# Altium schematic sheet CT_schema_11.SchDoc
size 281 x 153 mm
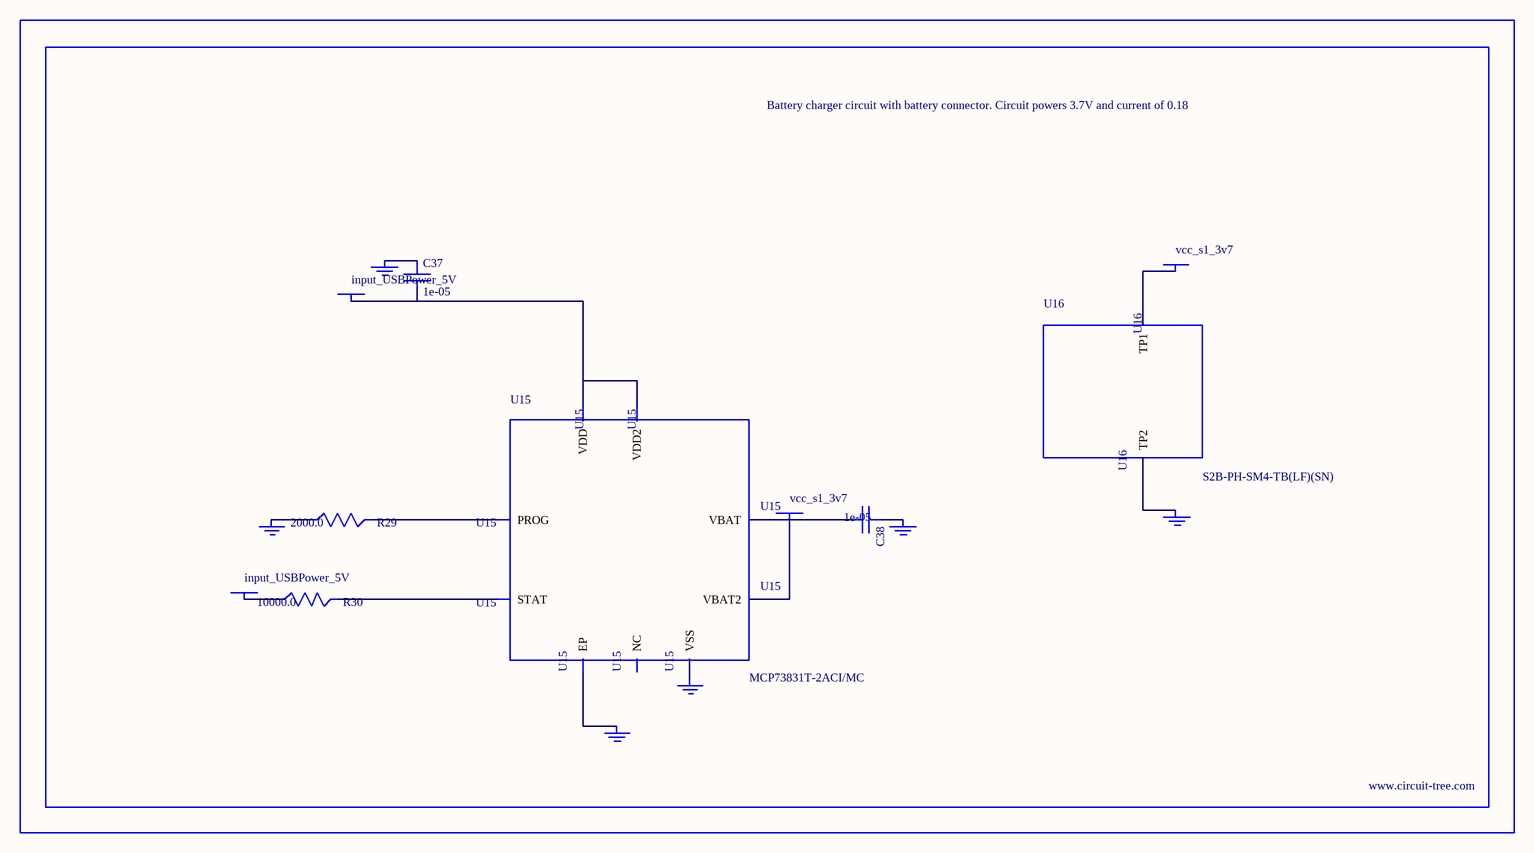
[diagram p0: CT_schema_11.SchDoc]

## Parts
BORDER10  (no value)
C37  1e-05  [C1206]
C38  1e-05  [C1206]
GND_INSTANCE_10_0  (no value)
GND_INSTANCE_10_1  (no value)
GND_INSTANCE_10_2  (no value)
GND_INSTANCE_10_3  (no value)
GND_INSTANCE_10_4  (no value)
GND_INSTANCE_10_5  (no value)
POWER_INSTANCE_10_0  input_USBPower_5V
POWER_INSTANCE_10_1  input_USBPower_5V
POWER_INSTANCE_10_2  vcc_s1_3v7
POWER_INSTANCE_10_3  vcc_s1_3v7
R29  2000.0  [R0603]
R30  10000.0  [R0603]
U15  MCP73831T-2ACI/MC  [DFN8_2X3MC]
U16  S2B-PH-SM4-TB(LF)(SN)  [JST-2-SMD]

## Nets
NetC37_1: C37.1 GND_INSTANCE_10_0.0(GND)
NetC37_2: C37.2 POWER_INSTANCE_10_0.0(PWR) U15.1(VDD) U15.2(VDD2)
NetC38_1: C38.1 GND_INSTANCE_10_1.0(GND)
NetC38_2: C38.2 POWER_INSTANCE_10_2.0(PWR) U15.3(VBAT) U15.4(VBAT2)
NetGND_INSTANCE_10_2_0: GND_INSTANCE_10_2.0(GND) R29.1
NetGND_INSTANCE_10_3_0: GND_INSTANCE_10_3.0(GND) U15.9(EP)
NetGND_INSTANCE_10_4_0: GND_INSTANCE_10_4.0(GND) U15.6(VSS)
NetGND_INSTANCE_10_5_0: GND_INSTANCE_10_5.0(GND) U16.2(TP2)
NetPOWER_INSTANCE_10_1_0: POWER_INSTANCE_10_1.0(PWR) R30.1
NetPOWER_INSTANCE_10_3_0: POWER_INSTANCE_10_3.0(PWR) U16.1(TP1)
NetR29_2: R29.2 U15.8(PROG)
NetR30_2: R30.2 U15.5(STAT)

Not connected (* = marked no-connect by the designer): U15 7(NC)

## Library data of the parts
BORDER10 = BORDER_PAGE10
C37 C38 = C1206C106K3RACTU
GND_INSTANCE_10_0-GND_INSTANCE_10_5 = GND
POWER_INSTANCE_10_0-POWER_INSTANCE_10_3 = PWR
R29 = RC0603JR-072KL
R30 = RC0603JR-0710KL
